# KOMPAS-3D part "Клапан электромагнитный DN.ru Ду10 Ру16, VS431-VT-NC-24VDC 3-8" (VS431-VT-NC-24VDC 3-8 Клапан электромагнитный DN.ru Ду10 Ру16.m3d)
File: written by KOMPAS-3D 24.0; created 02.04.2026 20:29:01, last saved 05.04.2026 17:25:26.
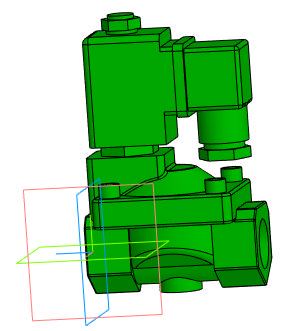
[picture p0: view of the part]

Document properties: Автор: artio; Полное имя файла: C:\Users\artio\OneDrive\Рабочий стол\Клапан электромагнитный DN.ru\VS431\VS431-VT-NC\VS431-VT-NC-24VDC\Ду10\VS431-VT-NC-24VDC 3-8 Клапан электромагнитный DN.ru Ду10 Ру16.m3d

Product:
- Body: Тело 1  | qty 1
    Масса: 1.030062
- Part/product: Клапан электромагнитный DN.ru Ду10 Ру16  | designation VS431-VT-NC-24VDC 3-8
    Масса: 0.62
    Раздел спецификации: Прочие изделия
    Примечание: D130-04753
    additional columns: ef56311e-7521-43dc-8291-0e6108b3d81d; VS400-ET-NC-220VAC 3-8; artio; c; Шероховатость не задана; Да

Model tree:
1. Операция без истории:1

Expressions: VS431-VT-NC-24VDC 3-8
